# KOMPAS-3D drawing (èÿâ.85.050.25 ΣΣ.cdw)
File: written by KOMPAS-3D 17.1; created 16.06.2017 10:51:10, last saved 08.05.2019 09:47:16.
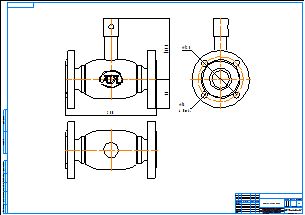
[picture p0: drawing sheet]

Sheet 1: A1, landscape

Title block, sheet 1: name: КШГ.85.050.25 фф; material: Внимание! Данный продукт является объектом авторского права ООО «Торговый Дом АДЛ». / Запрещается изменение, копирование, распространение / (в том числе путем копирования на другие сайты и ресурсы в Интернете) / или любое иное использование информации и объектов без предварительного / согласия правообладателя (ООО «Торговый Дом АДЛ»).; scale: 1:1; sheets: 1; organisation: ООО "Торговый дом АДЛ"; sheet format: A1; stored path: C:\Users\tra\Desktop\2д чертежи\Шаровые краны БИВАЛ\КШ_Бивал_серия_82_85\KOMPAS 2D\КШГ.85.050.25 фф.cdw

Views: Спереди 1, Проекционный вид 2, Проекционный вид 3
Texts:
  Klimkovich
  ADL
Dimensions and other numbers on the sheet: 250; 167,3; 80; 125; 18; 4 Отв.; 1:1; 1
